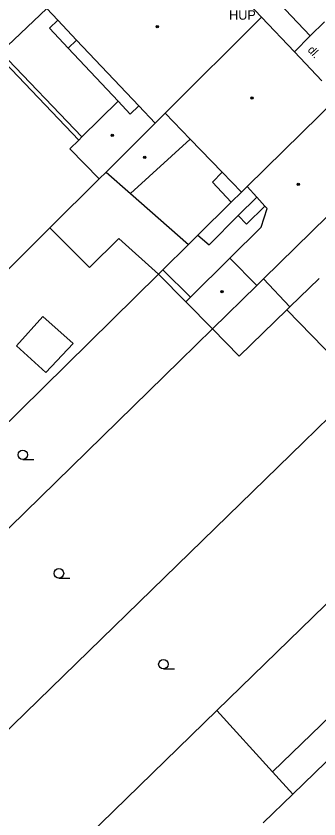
# Model space of a CAD drawing. Extents: x -596229 to -595156, y -1161237 to -1159376.
# Drawn here: x -596091.5 to -596067.4, y -1160551.1 to -1160487.4 of the extents above; entities that cross this region are included whole.
import ezdxf

# ---------------------------------------------------------------- set-up
doc = ezdxf.new("R2010")
doc.units = 0
for name, color, linetype in [('DOP - kresba z DSPS bez souradnic', 7, 'Continuous'), ('DOP - rozhrani ploch obecne', 7, 'Continuous'), ('Level 36', 7, 'Continuous'), ('Level 39', 7, 'Continuous'), ('TM - budovy zdene_ betonove - VP', 7, 'Continuous'), ('TM - chodniky - VP', 7, 'Continuous'), ('TM - letecke snimky - pomocna linie', 7, 'Continuous'), ('TM - popis objektu', 7, 'Continuous'), ('TM - popis povrchu', 7, 'Continuous'), ('TM - rozhrani ploch obecne - VP', 7, 'Continuous')]:
    doc.layers.add(name, color=color, linetype=linetype)

msp = doc.modelspace()

# ---------------------------------------------------------------- linework, layer by layer
at = {"layer": 'DOP - kresba z DSPS bez souradnic'}
for points in [[(-596092.68, -1160490.31), (-596086.24, -1160497.03)], [(-596075.12, -1160499.82), (-596075.88, -1160500.62)], [(-596075.88, -1160500.62), (-596074.4, -1160502.2)], [(-596073.86, -1160503.26), (-596072.38, -1160501.79)], [(-596073.19, -1160503.93), (-596071.74, -1160502.51)], [(-596076.16, -1160505.57), (-596073.86, -1160503.26)], [(-596073.86, -1160503.26), (-596073.19, -1160503.93)], [(-596077.05, -1160504.82), (-596076.16, -1160505.57)], [(-596079.82, -1160507.55), (-596077.63, -1160509.73)]]:
    msp.add_lwpolyline(points, dxfattribs=at)
at = {"layer": 'DOP - rozhrani ploch obecne'}
for points in [[(-596086.49, -1160497.27), (-596092.94, -1160490.55)], [(-596088.77, -1160504.24), (-596084.86, -1160500.35)], [(-596082.38, -1160501.51), (-596077.8, -1160505.56)], [(-596074.4, -1160502.2), (-596073.58, -1160501.4)], [(-596077.05, -1160504.82), (-596074.4, -1160502.2)], [(-596106.08, -1160521.47), (-596088.77, -1160504.24)], [(-596077.8, -1160505.56), (-596077.05, -1160504.82)], [(-596077.8, -1160505.56), (-596079.82, -1160507.55)], [(-596079.82, -1160507.55), (-596080.17, -1160507.9)], [(-596103.95, -1160531.33), (-596080.17, -1160507.9)], [(-596080.17, -1160507.9), (-596078, -1160510.09)], [(-596075.89, -1160512.24), (-596078.47, -1160514.77)], [(-596101.81, -1160537.59), (-596078.47, -1160514.77)], [(-596068.67, -1160521.24), (-596065.57, -1160518.21)], [(-596097.73, -1160549.52), (-596068.67, -1160521.24)], [(-596069.51, -1160549.13), (-596057.36, -1160537.34)], [(-596093.99, -1160560.46), (-596075.54, -1160542.5)], [(-596071.12, -1160547.37), (-596069.51, -1160549.13)], [(-596071.86, -1160551.41), (-596069.51, -1160549.13)]]:
    msp.add_lwpolyline(points, dxfattribs=at)
at = {"layer": 'Level 36'}
for p, q in [((-596090.93, -1160522.605), (-596090.055, -1160522.605)), ((-596088.06, -1160532.005), (-596087.185, -1160532.005)), ((-596079.78, -1160539.215), (-596078.905, -1160539.215))]:
    msp.add_line(p, q, dxfattribs=at)
for centre in [(-596090.93, -1160522.23), (-596088.06, -1160531.63), (-596079.78, -1160538.84)]:
    msp.add_circle(centre, 0.375, dxfattribs=at)
at = {"layer": 'Level 39'}
for centre, radius in [((-596080.27, -1160488.29), 0.09), ((-596080.27, -1160488.29), 0.0398), ((-596072.75, -1160493.93), 0.09), ((-596072.75, -1160493.93), 0.0398), ((-596083.83, -1160496.89), 0.09), ((-596083.83, -1160496.89), 0.0398), ((-596081.26, -1160498.64), 0.09), ((-596081.26, -1160498.64), 0.0398), ((-596069.09, -1160500.78), 0.09), ((-596069.09, -1160500.78), 0.0398), ((-596075.13, -1160509.3), 0.09), ((-596075.13, -1160509.3), 0.0398)]:
    msp.add_circle(centre, radius, dxfattribs=at)
at = {"layer": 'TM - budovy zdene_ betonove - VP'}
for points in [[(-596078.13, -1160481.06), (-596071.99, -1160487.53)], [(-596089.01, -1160486.85), (-596092.68, -1160490.31)], [(-596088.15, -1160487.76), (-596089.01, -1160486.85)], [(-596086.66, -1160489.34), (-596088.15, -1160487.76)], [(-596071.99, -1160487.53), (-596079.63, -1160495.14)], [(-596071.99, -1160487.53), (-596069.39, -1160490.27)], [(-596081.73, -1160494.57), (-596086.66, -1160489.34)], [(-596069.39, -1160490.27), (-596067.22, -1160492.57)], [(-596086.24, -1160497.03), (-596083.37, -1160494.2)], [(-596083.37, -1160494.2), (-596082.42, -1160495.22)], [(-596073.13, -1160500.95), (-596065.96, -1160493.89)], [(-596082.42, -1160495.22), (-596081.73, -1160494.57)], [(-596080.44, -1160495.94), (-596081.73, -1160494.57)], [(-596079.63, -1160495.14), (-596080.44, -1160495.94)], [(-596077.66, -1160497.19), (-596079.63, -1160495.14)], [(-596080.44, -1160495.94), (-596084.32, -1160499.81)], [(-596087.2, -1160497.97), (-596086.49, -1160497.27)], [(-596086.49, -1160497.27), (-596086.24, -1160497.03)], [(-596082.38, -1160501.51), (-596077.66, -1160497.19)], [(-596075.12, -1160499.82), (-596077.66, -1160497.19)], [(-596084.86, -1160500.35), (-596087.2, -1160497.97)], [(-596071.85, -1160508.29), (-596061.71, -1160498.37)], [(-596084.32, -1160499.81), (-596084.86, -1160500.35)], [(-596084.32, -1160499.81), (-596082.38, -1160501.51)], [(-596073.58, -1160501.4), (-596075.12, -1160499.82)], [(-596073.13, -1160500.95), (-596073.58, -1160501.4)], [(-596072.38, -1160501.79), (-596073.13, -1160500.95)], [(-596071.74, -1160502.51), (-596072.38, -1160501.79)], [(-596071.55, -1160502.71), (-596071.74, -1160502.51)], [(-596072.04, -1160504.19), (-596071.55, -1160502.71)], [(-596074.5, -1160506.63), (-596072.04, -1160504.19)], [(-596077.63, -1160509.73), (-596074.5, -1160506.63)], [(-596072.37, -1160508.8), (-596074.5, -1160506.63)], [(-596071.85, -1160508.29), (-596072.37, -1160508.8)], [(-596071.85, -1160508.29), (-596069.76, -1160510.51)], [(-596067.43, -1160508.24), (-596069.76, -1160510.51)], [(-596072.37, -1160508.8), (-596075.89, -1160512.24)], [(-596078, -1160510.09), (-596077.63, -1160509.73)], [(-596075.89, -1160512.24), (-596078, -1160510.09)], [(-596062.07, -1160529.39), (-596068.89, -1160536.02)], [(-596071.12, -1160547.37), (-596054.94, -1160531.72)], [(-596068.89, -1160536.02), (-596075.54, -1160542.5)], [(-596075.54, -1160542.5), (-596071.12, -1160547.37)]]:
    msp.add_lwpolyline(points, dxfattribs=at)
at = {"layer": 'TM - chodniky - VP'}
for points in [[(-596075.46, -1160480.67), (-596075.26, -1160481.18), (-596074.53, -1160482.23), (-596068.14, -1160489)], [(-596067, -1160487.89), (-596068.14, -1160489)]]:
    msp.add_lwpolyline(points, dxfattribs=at)
at = {"layer": 'TM - letecke snimky - pomocna linie'}
for points in [[(-596088.77, -1160504.24), (-596085.65, -1160507.37), (-596083.32, -1160505.08), (-596080.17, -1160507.9)], [(-596070, -1160510.74), (-596073.76, -1160514.41)], [(-596069.76, -1160510.51), (-596070, -1160510.74)], [(-596064.11, -1160516.79), (-596070, -1160510.74)], [(-596089.34, -1160511.26), (-596091.43, -1160513.59), (-596089.1, -1160515.7), (-596086.93, -1160513.4)], [(-596086.93, -1160513.4), (-596089.34, -1160511.26)], [(-596075.89, -1160512.24), (-596073.76, -1160514.41)]]:
    msp.add_lwpolyline(points, dxfattribs=at)
at = {"layer": 'TM - rozhrani ploch obecne - VP'}
for points in [[(-596088.15, -1160487.76), (-596088.82, -1160488.39), (-596087.33, -1160489.98)], [(-596068.14, -1160489), (-596069.39, -1160490.27)], [(-596086.66, -1160489.34), (-596087.33, -1160489.98)], [(-596087.33, -1160489.98), (-596083.37, -1160494.2)]]:
    msp.add_lwpolyline(points, dxfattribs=at)

# ---------------------------------------------------------------- texts
at = {"layer": 'TM - popis objektu'}
msp.add_text('HUP', height=0.75, dxfattribs=at).set_placement((-596074.57, -1160487.73))
at = {"layer": 'TM - popis povrchu'}
msp.add_text('dl.', height=0.65, rotation=312.62, dxfattribs=at).set_placement((-596068.39, -1160490.17))

doc.saveas('drawing.dxf')
